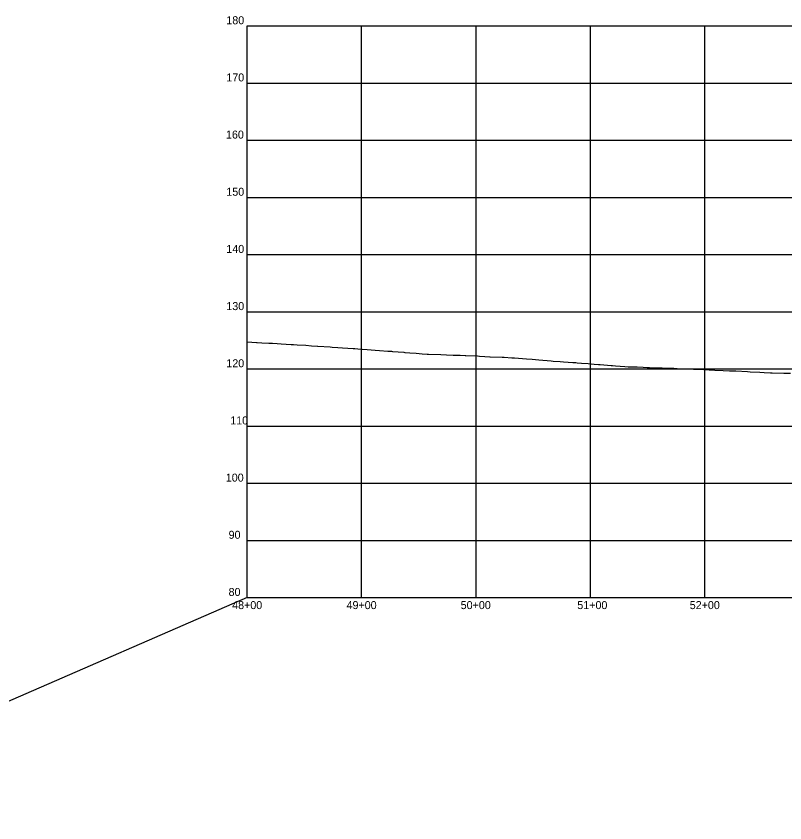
# Model space of a CAD drawing. Extents: x 1191541 to 1200065, y 1475807 to 1480451.
# Drawn here: x 1196514 to 1197186, y 1477804 to 1478510 of the extents above; entities that cross this region are included whole.
import ezdxf

# ---------------------------------------------------------------- set-up
doc = ezdxf.new("R2010")
doc.units = 0
for name, color, linetype in [('R_Exist Surface', 7, 'Continuous'), ('R_Grid', 7, 'Continuous'), ('R_No Plot', 7, 'Continuous'), ('R_Proposed Const Limits_Hand', 7, 'Continuous'), ('R_Water', 7, 'Continuous')]:
    doc.layers.add(name, color=color, linetype=linetype)

msp = doc.modelspace()

# ---------------------------------------------------------------- linework, layer by layer
at = {"layer": 'R_Exist Surface'}
msp.add_lwpolyline([(1196715.85, 1478224.67), (1196724.04, 1478224.24), (1196724.36, 1478224.22), (1196728.52, 1478224), (1196734.77, 1478223.66), (1196737.78, 1478223.49), (1196741.9, 1478223.26), (1196745.49, 1478223.03), (1196754.27, 1478222.46), (1196756.22, 1478222.36), (1196759.58, 1478222.18), (1196766.95, 1478221.69), (1196772.02, 1478221.34), (1196777.26, 1478221.06), (1196777.68, 1478221.03), (1196788.41, 1478220.28), (1196790.01, 1478220.16), (1196794.95, 1478219.87), (1196799.14, 1478219.57), (1196808.28, 1478218.89), (1196809.87, 1478218.8), (1196812.64, 1478218.62), (1196816.36, 1478218.37), (1196820.6, 1478218.06), (1196827.76, 1478217.52), (1196831.33, 1478217.25), (1196838.61, 1478216.69), (1196842.05, 1478216.44), (1196842.88, 1478216.38), (1196852.78, 1478215.59), (1196853.61, 1478215.53), (1196858.02, 1478215.19), (1196863.51, 1478214.75), (1196868.76, 1478214.31), (1196873.14, 1478213.97), (1196874.24, 1478213.94), (1196884.97, 1478213.64), (1196885.1, 1478213.64), (1196889.96, 1478213.36), (1196895.7, 1478213.19), (1196901.85, 1478212.99), (1196906.43, 1478212.72), (1196906.78, 1478212.7), (1196917.16, 1478212.35), (1196918.79, 1478212.29), (1196923.59, 1478211.99), (1196927.89, 1478211.73), (1196928.31, 1478211.7), (1196938.61, 1478211.34), (1196940.41, 1478211.27), (1196947.03, 1478210.85), (1196949.34, 1478210.67), (1196960.07, 1478209.82), (1196964.85, 1478209.44), (1196970.8, 1478208.96), (1196981.53, 1478208.09), (1196983.18, 1478207.95), (1196989.28, 1478207.53), (1196992.26, 1478207.33), (1197000.4, 1478206.77), (1197002.99, 1478206.54), (1197004.13, 1478206.44), (1197007.89, 1478206.11), (1197013.72, 1478205.7), (1197018.98, 1478205.32), (1197022.82, 1478204.98), (1197024.45, 1478204.86), (1197033.82, 1478204.18), (1197035.17, 1478204.05), (1197037.61, 1478203.83), (1197045.9, 1478203.21), (1197048.68, 1478203), (1197052.11, 1478202.9), (1197056.63, 1478202.73), (1197061.93, 1478202.54), (1197065.4, 1478202.43), (1197067.36, 1478202.35), (1197075.2, 1478202.06), (1197078.09, 1478201.96), (1197078.6, 1478201.94), (1197088.46, 1478201.56), (1197088.82, 1478201.54), (1197091.69, 1478201.44), (1197099.55, 1478201.12), (1197101.72, 1478201.03), (1197105.94, 1478200.91), (1197110.28, 1478200.7), (1197119.59, 1478200.25), (1197121.01, 1478200.21), (1197124.5, 1478200.1), (1197131.73, 1478199.74), (1197137.48, 1478199.45), (1197142.46, 1478199.28), (1197142.8, 1478199.27), (1197153.19, 1478198.73), (1197155.37, 1478198.62), (1197163.92, 1478198.16), (1197167.77, 1478197.95), (1197173.26, 1478197.74), (1197174.65, 1478197.71), (1197184.83, 1478197.43), (1197185.38, 1478197.42), (1197190.76, 1478197.33)], dxfattribs=at)
at = {"layer": 'R_Grid'}
for p, q in [((1196715.85, 1478500.99), (1198215.85, 1478500.99)), ((1196715.85, 1478500.99), (1198215.85, 1478500.99)), ((1196815.85, 1478000.99), (1196815.85, 1478500.99)), ((1196915.85, 1478000.99), (1196915.85, 1478500.99)), ((1197015.85, 1478000.99), (1197015.85, 1478500.99)), ((1197115.85, 1478000.99), (1197115.85, 1478500.99)), ((1196715.85, 1478450.99), (1198215.85, 1478450.99)), ((1196715.85, 1478400.99), (1198215.85, 1478400.99)), ((1196715.85, 1478350.99), (1198215.85, 1478350.99)), ((1196715.85, 1478300.99), (1198215.85, 1478300.99)), ((1196715.85, 1478250.99), (1198215.85, 1478250.99)), ((1196715.85, 1478200.99), (1198215.85, 1478200.99)), ((1196715.85, 1478150.99), (1198215.85, 1478150.99)), ((1196715.85, 1478100.99), (1198215.85, 1478100.99)), ((1196715.85, 1478050.99), (1198215.85, 1478050.99))]:
    msp.add_line(p, q, dxfattribs=at)
at = {"layer": 'R_No Plot'}
msp.add_line((1196715.85, 1478000.99), (1196262.44, 1477804.03), dxfattribs=at)
at = {"layer": 'R_Water'}
for q in [(1196715.85, 1478500.99), (1198215.85, 1478000.99)]:
    msp.add_line((1196715.85, 1478000.99), q, dxfattribs=at)

# ---------------------------------------------------------------- texts
at = {"layer": 'R_Proposed Const Limits_Hand'}
for s, height, p in [('180', 7, (1196697.56, 1478502.49)), ('180', 7, (1196697.56, 1478502.49)), ('170', 7, (1196697.56, 1478452.49)), ('160', 7, (1196697.27, 1478402.49)), ('150', 7, (1196697.56, 1478352.49)), ('140', 7, (1196697.56, 1478302.49)), ('130', 7, (1196697.56, 1478252.49)), ('120', 7, (1196697.56, 1478202.49)), ('110', 7, (1196700.96, 1478152.49)), ('100', 7, (1196697.09, 1478102.49)), ('90', 7, (1196699.54, 1478052.49)), ('80', 7, (1196699.54, 1478002.49)), ('-', 0.0001, (1196715.85, 1478000.99)), ('48+00', 7, (1196702.64, 1477990.99)), ('49+00', 7, (1196802.64, 1477990.99)), ('50+00', 7, (1196902.41, 1477990.99)), ('51+00', 7, (1197004.35, 1477990.99)), ('52+00', 7, (1197102.64, 1477990.99))]:
    msp.add_text(s, height=height, dxfattribs=at).set_placement(p)

doc.saveas('drawing.dxf')
